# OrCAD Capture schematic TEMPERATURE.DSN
size A; company: mycompany; note: line1; note: line 2
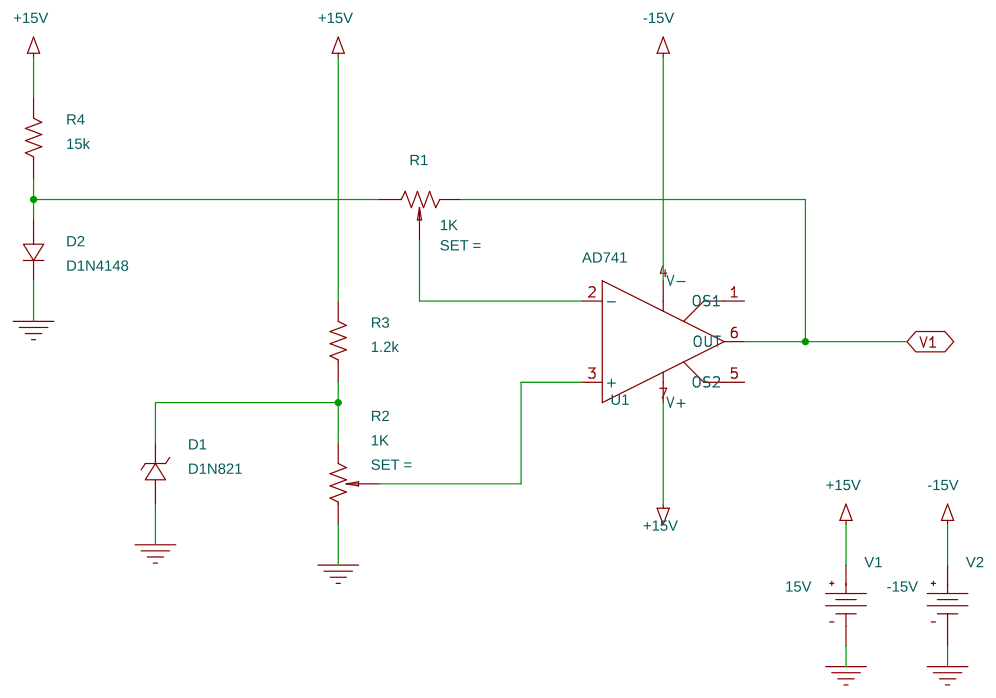
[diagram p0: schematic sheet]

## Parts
D1  D1N821  [DO-204AH]
D2  D1N4148  [DO-35]
R1  1K  [VRES10]
R2  1K  [VRES10]
R3  1.2k  [AX/RC05]
R4  15k  [AX/RC05]
U1  AD741  [DIP.100/8/W.300/L.450]
V1  VDC
V2  VDC

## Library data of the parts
D1 = D1N821
D2 = D1N4148
R1 R2 = POT
R3 R4 = R
U1 = AD741
V1 = VDC: DC: 15V
V2 = VDC: DC: -15V

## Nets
+15V: R3.2 R4.2 U1.7(V+) V1.0(+)
-15V: U1.4(V-) V2.0(+)
V1: R1.3(2) U1.6(OUT)
0: D1.1 D2.2 R2.1 V1.1(-) V2.1(-)
N00127: R1.2(t) U1.2(-)
N00187: D2.1 R1.1 R4.1
N00212: R2.2(t) U1.3(+)
N00345: D1.2 R2.3(2) R3.1

Not connected (* = marked no-connect by the designer): U1 1(OS1) 5(OS2)
